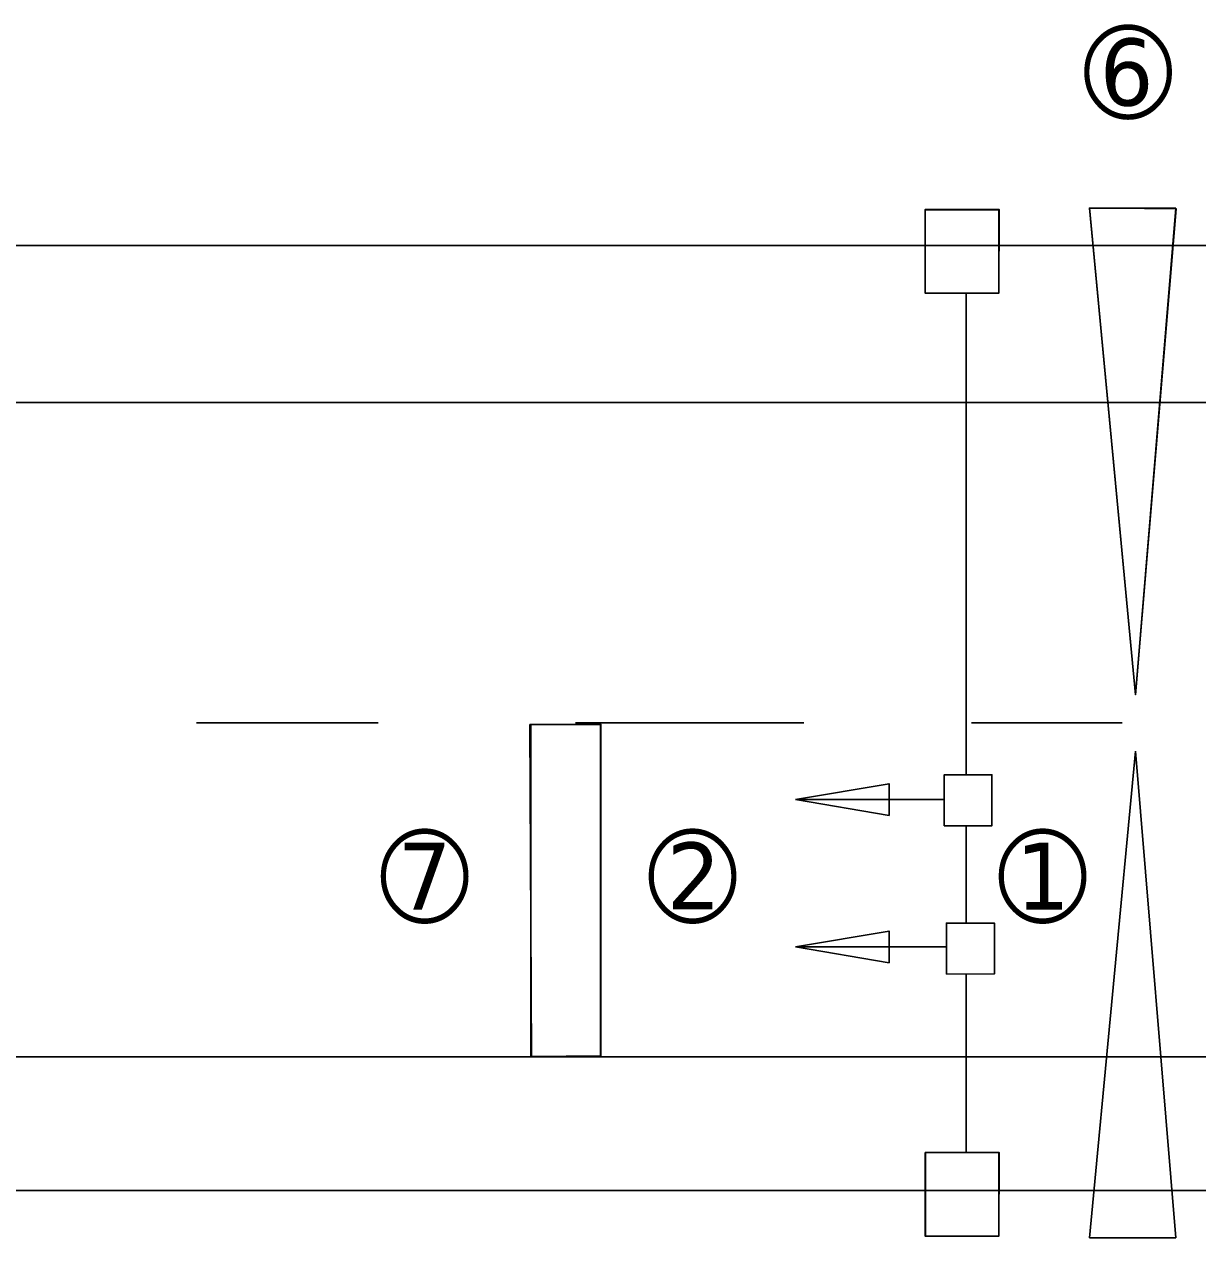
# Model space of a CAD drawing. Extents: x 15 to 764, y 7 to 487.
# Drawn here: x 77.2 to 126.2, y 391.2 to 441.9 of the extents above; entities that cross this region are included whole.
import ezdxf

# ---------------------------------------------------------------- set-up
doc = ezdxf.new("R2010")
doc.units = 0
for name, color, linetype in [('Default', 7, 'Continuous'), ('Dimension', 7, 'Continuous'), ('TextStructures', 7, 'Continuous')]:
    doc.layers.add(name, color=color, linetype=linetype)

msp = doc.modelspace()

# ---------------------------------------------------------------- linework, layer by layer
at = {"layer": 'Default'}
for p, q in [((121.719, 434.19), (125.331, 434.19)), ((123.648, 413.864), (121.719, 434.19)), ((122.711, 434.19), (121.724, 434.19)), ((125.331, 434.19), (123.648, 413.864)), ((123.648, 413.864), (125.328, 434.154)), ((22.063, 432.626), (366.864, 432.626)), ((116.574, 430.635), (116.574, 410.514)), ((22.063, 426.064), (366.864, 426.064)), ((84.438, 412.687), (92.021, 412.687)), ((100.262, 412.687), (109.793, 412.687)), ((116.787, 412.687), (123.081, 412.687)), ((123.648, 411.511), (121.719, 391.184)), ((123.648, 411.511), (121.719, 391.184)), ((125.331, 391.184), (123.648, 411.511)), ((125.331, 391.184), (123.648, 411.511)), ((115.647, 409.486), (109.445, 409.486)), ((116.574, 408.388), (116.574, 404.326)), ((115.756, 403.33), (109.445, 403.33)), ((116.574, 402.199), (116.574, 394.739)), ((22.063, 398.745), (366.864, 398.745)), ((22.063, 393.153), (366.864, 393.153)), ((121.719, 391.184), (125.331, 391.184)), ((121.719, 391.184), (125.331, 391.184))]:
    msp.add_line(p, q, dxfattribs=at)
for points in [[(114.853, 434.126), (117.954, 434.126), (117.941, 430.638), (114.853, 430.638)], [(114.857, 430.635), (114.857, 434.121), (117.937, 434.121), (117.937, 430.635)], [(121.723, 434.203), (125.345, 434.154), (123.648, 413.864)], [(98.426, 398.752), (101.304, 398.788), (101.304, 412.613), (98.354, 412.613)], [(101.321, 398.745), (101.321, 412.62), (98.397, 412.62), (98.397, 398.745)], [(115.653, 410.523), (117.643, 410.523), (117.643, 408.392), (115.653, 408.392)], [(115.647, 408.388), (115.647, 410.514), (117.64, 410.514), (117.64, 408.388)], [(115.747, 404.326), (117.747, 404.326), (117.747, 402.203), (115.753, 402.196)], [(117.747, 402.203), (117.747, 404.326), (115.747, 404.326), (115.753, 402.196)], [(114.857, 394.739), (114.857, 391.253), (117.937, 391.253), (117.937, 394.739)], [(114.868, 394.748), (117.948, 394.748), (117.938, 391.256), (114.868, 391.256)]]:
    msp.add_lwpolyline(points, close=True, dxfattribs=at)
for points in [[(117.937, 430.638), (117.937, 434.121), (114.857, 434.121), (114.857, 430.638)], [(121.724, 434.19), (123.648, 413.864)], [(125.328, 434.154), (122.711, 434.19)], [(114.857, 430.638), (117.937, 430.638)], [(101.304, 412.62), (98.397, 412.62), (98.397, 404.252)], [(98.426, 398.752), (101.304, 398.788), (101.304, 412.613)], [(117.64, 408.392), (117.64, 410.514), (115.647, 410.514), (115.647, 408.392)], [(115.653, 408.392), (117.64, 408.392)], [(98.397, 404.252), (98.426, 398.752)], [(117.937, 391.256), (117.937, 394.739), (114.868, 394.739)], [(114.868, 394.739), (114.868, 391.256), (117.937, 391.256)]]:
    msp.add_lwpolyline(points, dxfattribs=at)
at = {"layer": 'Dimension'}
for points in [[(109.445, 409.486), (113.35, 408.824), (113.35, 410.147)], [(109.445, 403.33), (113.35, 402.668), (113.35, 403.991)]]:
    msp.add_lwpolyline(points, close=True, dxfattribs=at)

# ---------------------------------------------------------------- texts
at = {"layer": 'TextStructures'}
for s, p in [('➅', (121.482, 438.122)), ('➆', (92.11, 404.537)), ('➁', (103.295, 404.537)), ('➀', (117.911, 404.537))]:
    msp.add_text(s, height=3.5, dxfattribs=at).set_placement(p)

doc.saveas('drawing.dxf')
